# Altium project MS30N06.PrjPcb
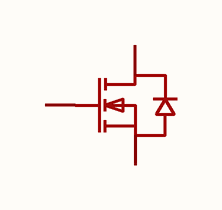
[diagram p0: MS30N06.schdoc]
1 sheet, 1 parts. Net scope: global (net labels, ports and power ports of the same name join across sheets).

## Sheet MS30N06.schdoc
size 127 x 101 mm

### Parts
Q?  ms30n06  [TO-252-2_L6.6-W6.0-P4.58-LS10.1-BR]  (value not drawn)

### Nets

Not connected (* = marked no-connect by the designer): Q? 1(G) 2(D) 3(S)

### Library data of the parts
Q? = ms30n06: 数量:1个N沟道;漏源电压(Vdss):60V;连续漏极电流(Id):30A;导通电阻(RDS(on)):25mΩ@10V;耗散功率(Pd):34.7W;阈值电压(Vgs(th)):2.5V@250uA;; Manufacturer: MSKSEMI(美森科); AddInBom: yes; ModelId: 15201b043553414fa3153da7281ca125; ModelTransform: 259.842,395.6685,0,90,0,0,-38.543,0,0; Number: 1个N沟道; Drain to Source Voltage: 60V; Current - Continuous Drain(Id): 30A; Pd - Power Dissipation: 34.7W; Gate Charge(Qg): 12.6nC@4.5V; Input Capacitance(Ciss): 1.378nF; Reverse Transfer Capacitance (Crss@Vds): 64pF; Type: N沟道; Output Capacitance(Coss): 86pF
